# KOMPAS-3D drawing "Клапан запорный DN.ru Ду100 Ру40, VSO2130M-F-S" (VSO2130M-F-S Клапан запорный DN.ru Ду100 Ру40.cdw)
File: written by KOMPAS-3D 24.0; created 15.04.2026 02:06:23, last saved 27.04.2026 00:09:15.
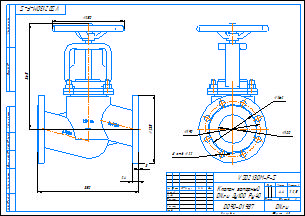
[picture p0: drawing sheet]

Document properties: Автор: DN.ru; Форматы листов документа: A3; Полное имя файла: VSO2130M-F-S Клапан запорный DN.ru Ду100 Ру40.m3d; Масса: 44; Наименование: Клапан запорный DN.ru Ду100 Ру40; Количество листов документа: 1; Примечание: D090-01987

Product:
- Part/product: Клапан запорный DN.ru Ду100 Ру40  | designation VSO2130M-F-S
    Масса: 44
    Раздел спецификации: Прочие изделия
    Примечание: D090-01987

Views: Вид 1, Вид:1, Проекционный вид 2
Referenced files in C:\Работа\VSO2130M-F-S Клапан запорный DN.ru\DN20\: VSO2130M-F-S DN20 PN40  Клапан запорный сильфонный DN.ru.m3d
Referenced files in C:\Работа\VSO2130M-F-S Клапан запорный DN.ru\DN100\: VSO2130M-F-S Клапан запорный DN.ru Ду100 Ру40.m3d
Referenced files in C:\Program Files\ASCON\KOMPAS-3D v24\Templates\: Чертеж_DN.ru.cdt
Referenced files in C:\Работа\ГОТОВЫЕ ИСХОДНИКИ\VSO2130M-F-S Клапан запорный сальниковый DN.ru Ду15-100 Ру40\DN100\: VSO2130M-F-S Клапан запорный DN.ru Ду100 Ру40.m3d
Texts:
  VSO2130M-F-S
  Чертеж_DN.ru.cdt
  Клапан запорный
  DN.ru Ду100 Ру40
  Клапан запорный DN.ru Ду100 Ру40
  VSO2130M-F-S Клапан запорный DN.ru Ду100 Ру40
Dimensions and other numbers on the sheet: 0; 3; 2; 4; 235; 24; 350; 365; 250; 5; 100; 162; 190; 8 отв.; 22; 1:2,5; 1; 44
